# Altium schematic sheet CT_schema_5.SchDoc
size 226 x 144 mm
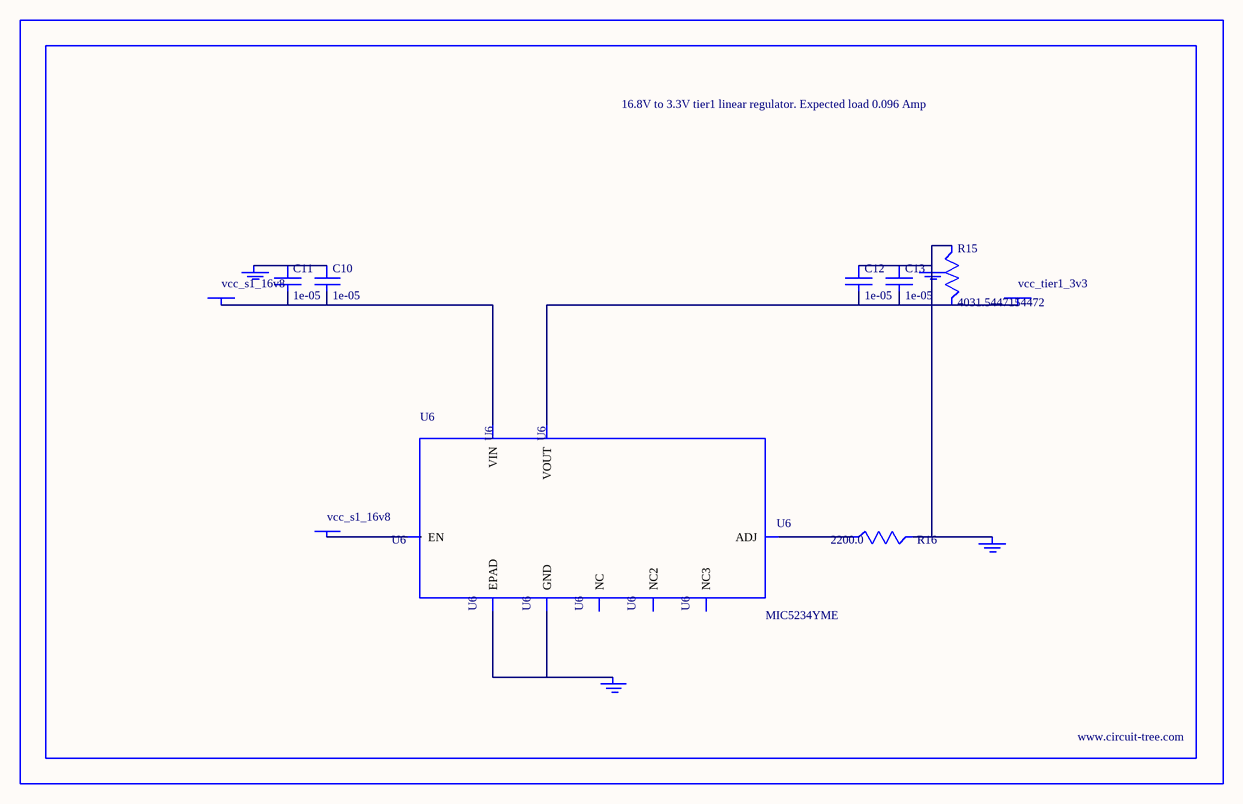
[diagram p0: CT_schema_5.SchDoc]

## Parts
BORDER4  (no value)
C10  1e-05  [C1210]
C11  1e-05  [C1210]
C12  1e-05  [C1210]
C13  1e-05  [C1210]
GND_INSTANCE_4_0  (no value)
GND_INSTANCE_4_1  (no value)
GND_INSTANCE_4_2  (no value)
GND_INSTANCE_4_3  (no value)
POWER_INSTANCE_4_0  vcc_tier1_3v3
POWER_INSTANCE_4_1  vcc_s1_16v8
POWER_INSTANCE_4_2  vcc_s1_16v8
R15  4031.5447154472  [R0603]
R16  2200.0  [R0603]
U6  MIC5234YME  [SOIC-8_EP]

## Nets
NetC10_1: C10.1 C11.1 GND_INSTANCE_4_3.0(GND)
NetC10_2: C10.2 C11.2 POWER_INSTANCE_4_2.0(PWR) U6.8(VIN)
NetC12_1: C12.1 C13.1 GND_INSTANCE_4_0.0(GND) GND_INSTANCE_4_1.0(GND) R15.1 R16.2
NetC12_2: C12.2 C13.2 POWER_INSTANCE_4_0.0(PWR) R15.2 U6.1(VOUT)
NetGND_INSTANCE_4_2_0: GND_INSTANCE_4_2.0(GND) U6.7(GND) U6.EPAD
NetPOWER_INSTANCE_4_1_0: POWER_INSTANCE_4_1.0(PWR) U6.5(EN)
NetR16_1: R16.1 U6.4(ADJ)

Not connected (* = marked no-connect by the designer): U6 2(NC) 3(NC2) 6(NC3)

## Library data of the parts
BORDER4 = BORDER_PAGE4
C10-C13 = C1210C106K5PACTU
GND_INSTANCE_4_0-GND_INSTANCE_4_3 = GND
POWER_INSTANCE_4_0-POWER_INSTANCE_4_2 = PWR
R15 = R15
R16 = RC0603JR-072K2L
